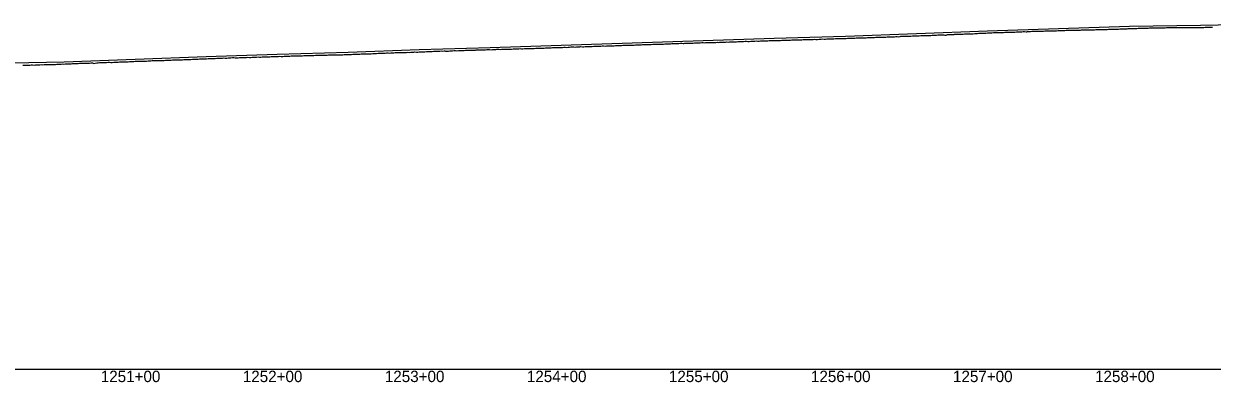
# Model space of a CAD drawing. Extents: x -3793 to 50787, y -1075 to 6138.
# Drawn here: x 12399 to 13236, y 2991 to 3243 of the extents above; entities that cross this region are included whole.
import ezdxf

# ---------------------------------------------------------------- set-up
doc = ezdxf.new("R2010")
doc.units = 0
for name, color, linetype in [('RD_DDB_Profile_EX', 7, 'Continuous'), ('RD_DDB_Profile_PR', 7, 'Continuous'), ('RD_DDB_StaTX', 7, 'Continuous'), ('RD_GPK_Profile_Cell', 7, 'Continuous')]:
    doc.layers.add(name, color=color, linetype=linetype)

msp = doc.modelspace()

# ---------------------------------------------------------------- linework, layer by layer
at = {"layer": 'RD_DDB_Profile_EX'}
for points in [[(13072.306264, 3236.75838), (13073.304099, 3236.70882), (13074.302047, 3236.758805), (13075.292662, 3236.857655), (13075.862268, 3236.857435), (13076.297838, 3236.857915), (13077.295896, 3236.90776), (13078.294157, 3236.956925), (13079.572775, 3236.95617), (13080.577836, 3237.006365), (13081.575804, 3237.15508), (13082.573912, 3237.155535), (13083.179478, 3237.215955), (13083.571855, 3237.254535), (13084.569685, 3237.25478), (13085.574724, 3237.25486), (13086.572591, 3237.354305), (13087.577599, 3237.3546), (13088.568537, 3237.35463), (13089.573545, 3237.404485), (13090.571408, 3237.404325), (13091.569215, 3237.453445), (13092.574194, 3237.453595), (13093.572001, 3237.50288), (13094.576979, 3237.502865), (13095.567796, 3237.403175), (13096.565616, 3237.55208), (13097.813897, 3237.688355), (13098.568459, 3237.8011), (13099.57336, 3237.80105), (13100.571042, 3237.75032), (13101.575949, 3237.800195), (13102.616794, 3237.85), (13103.566623, 3237.84777), (13104.571868, 3237.69821), (13105.131107, 3237.837095), (13105.571994, 3237.945745), (13106.577408, 3237.945795), (13107.577653, 3237.99183), (13108.575683, 3238.08816), (13109.572659, 3238.138465), (13110.572439, 3238.08537), (13111.57772, 3238.13844), (13112.577541, 3238.18377), (13113.875604, 3238.182045), (13114.872886, 3238.18296), (13115.870396, 3238.234645), (13116.867801, 3238.28622), (13117.872954, 3238.335305), (13118.870455, 3238.33979), (13119.867865, 3238.39037), (13120.86535, 3238.43813), (13121.870692, 3238.44062), (13122.868177, 3238.49099), (13123.871794, 3238.49097), (13124.869342, 3238.49199), (13125.874521, 3238.541645), (13127.082736, 3238.551605), (13127.869629, 3238.59012), (13128.867196, 3238.641445), (13129.872629, 3238.689575), (13130.870198, 3238.641615), (13131.867767, 3238.68831), (13132.865404, 3238.786915), (13133.870775, 3238.83896), (13134.399946, 3238.812585), (13134.868387, 3238.78972), (13135.866127, 3238.79165), (13136.863787, 3238.89099), (13137.875257, 3238.987915), (13138.872996, 3238.98792), (13139.870656, 3238.99108), (13140.868395, 3238.94045), (13141.873842, 3238.98604), (13142.871573, 3238.985775), (13143.653405, 3239.039225), (13144.651288, 3239.03983), (13145.649082, 3239.08885), (13146.660711, 3239.089555), (13147.658595, 3239.139395), (13148.656387, 3239.18838), (13149.034366, 3239.207245), (13149.654377, 3239.238075), (13150.652334, 3239.23678), (13151.658457, 3239.23691), (13152.656528, 3239.238625), (13153.660107, 3239.281735), (13154.658059, 3239.33018), (13155.656127, 3239.3276), (13156.654132, 3239.3779), (13157.660383, 3239.42734), (13158.658636, 3239.3716), (13159.656753, 3239.42185), (13160.660469, 3239.381655), (13161.658725, 3239.47849), (13162.664934, 3239.57472), (13163.668785, 3239.622465), (13164.661486, 3239.62139), (13165.659763, 3239.57025), (13166.663611, 3239.61644), (13167.662063, 3239.66361)], [(13167.662063, 3239.66361), (13168.668374, 3239.66355), (13169.666848, 3239.70879), (13170.665122, 3239.76112), (13170.985995, 3239.76072), (13171.663507, 3239.75581), (13172.662174, 3239.80617), (13173.674111, 3239.86908), (13174.692091, 3239.91589), (13175.647174, 3239.914745), (13176.495886, 3239.963505), (13177.499968, 3240.018275), (13178.496861, 3240.01596), (13179.501313, 3240.01219), (13180.498485, 3240.06419), (13181.502407, 3240.11442), (13182.499575, 3240.16466), (13183.504027, 3240.2114), (13184.49436, 3240.26329), (13185.620414, 3240.254215), (13186.495987, 3240.208925), (13187.492701, 3240.31275), (13188.4972, 3240.37356), (13189.494352, 3240.420725), (13190.498629, 3240.370725), (13191.495587, 3240.46975), (13192.500087, 3240.516925), (13192.937624, 3240.53987), (13193.497042, 3240.558655), (13194.495043, 3240.550515), (13195.519098, 3240.578595), (13196.496773, 3240.52966), (13197.493571, 3240.57058), (13198.49812, 3240.620155), (13199.49528, 3240.581695), (13200.492105, 3240.630505), (13201.496706, 3240.62992), (13202.493899, 3240.63098), (13203.498179, 3240.67693), (13204.495376, 3240.728175), (13205.493597, 3240.727905), (13206.490459, 3240.727855), (13207.572044, 3240.7261), (13208.492305, 3240.72811), (13209.496627, 3240.72595), (13210.73181, 3240.779935), (13211.727999, 3240.778465), (13212.716518, 3240.776345), (13213.713849, 3240.727335), (13214.889253, 3240.77705), (13215.715467, 3240.7771), (13216.712546, 3240.82777), (13217.717349, 3240.7788), (13218.714428, 3240.78055), (13219.711508, 3240.83001), (13220.710047, 3240.827075), (13221.707316, 3240.775145), (13222.206463, 3240.79933), (13222.711973, 3240.82241), (13223.709128, 3240.822785), (13224.713803, 3240.878005), (13225.711171, 3240.826885), (13226.708326, 3240.82853), (13227.713176, 3240.871645), (13228.710331, 3240.8248), (13229.715232, 3240.87477), (13230.712467, 3240.920365), (13231.709702, 3240.92041), (13232.714424, 3240.97168), (13233.711902, 3240.97324), (13234.716823, 3241.023375), (13235.714058, 3241.06842)], [(12785.161714, 3227.131865), (12786.1683, 3227.13607), (12787.170487, 3226.94517), (12788.164201, 3227.17857), (12789.166399, 3227.237655), (12790.164483, 3227.243325), (12790.491087, 3227.25927), (12791.166854, 3227.28867), (12792.169305, 3227.240745), (12793.16327, 3227.158285), (12794.169761, 3227.348135), (12795.172211, 3227.393415), (12796.165543, 3227.39367), (12797.172358, 3227.4871), (12798.166415, 3227.48717), (12799.169122, 3227.489035), (12800.171829, 3227.583735), (12801.170409, 3227.58551), (12802.173124, 3227.583785), (12803.167376, 3227.587345), (12804.170109, 3227.72815), (12805.176804, 3227.735715), (12806.171327, 3227.78912), (12807.159993, 3227.77991), (12808.162271, 3227.73218), (12809.161123, 3227.829945), (12810.163394, 3227.92425), (12810.607658, 3227.923805), (12811.607457, 3227.97565), (12812.607261, 3227.977445), (12813.608652, 3227.97141), (12814.608492, 3227.93842), (12815.608331, 3228.035945), (12816.601985, 3228.085405), (12817.609091, 3228.131475), (12818.608943, 3228.179205), (12819.759926, 3228.18809), (12820.603512, 3228.23359), (12821.610676, 3228.28317), (12822.610557, 3228.284335), (12823.604704, 3228.32994), (12824.604578, 3228.28841), (12825.61175, 3228.288015), (12826.605897, 3228.38735), (12827.077136, 3228.387865), (12827.605794, 3228.39193), (12828.60571, 3228.431955), (12829.607192, 3228.47554), (12830.60711, 3228.537525), (12831.607029, 3228.584715), (12832.601218, 3228.630055), (12833.608424, 3228.675595), (12834.608353, 3228.726485), (12835.60259, 3228.68633), (12836.609825, 3228.685405), (12837.609788, 3228.782185), (12838.604033, 3228.834775), (12839.603521, 3228.87755), (12840.610737, 3228.876525), (12841.711556, 3228.926985), (12842.604985, 3228.929475), (12843.60499, 3228.97197), (12844.61223, 3229.07455), (12845.226336, 3229.07937), (12846.226207, 3229.02966), (12847.226078, 3229.083845), (12848.225949, 3229.088), (12849.215929, 3229.138285), (12850.215757, 3229.188545), (12851.2158, 3229.28088), (12852.207881, 3229.340185), (12853.207715, 3229.340435), (12854.207759, 3229.336725), (12855.207594, 3229.38699), (12856.345975, 3229.47974), (12857.207588, 3229.479635), (12858.208176, 3229.48693), (12859.213328, 3229.534995), (12860.212895, 3229.58123), (12861.213473, 3229.67385), (12862.213445, 3229.627475), (12863.213616, 3229.53447), (12863.663185, 3229.601775), (12864.213658, 3229.68067), (12865.206001, 3229.73913), (12866.206303, 3229.688635), (12867.206405, 3229.738375), (12868.207115, 3229.741655), (12869.206804, 3229.748635), (12870.207517, 3229.840955), (12871.207644, 3229.88325), (12872.207448, 3229.913855), (12873.208297, 3229.916815), (12874.213302, 3229.882985), (12875.214143, 3230.021065), (12876.214358, 3230.112885), (12877.214139, 3230.09675), (12878.297605, 3230.050365), (12879.207615, 3230.14303), (12880.208164, 3230.13754), (12881.208501, 3230.144145)], [(12881.208501, 3230.144145), (12882.209495, 3230.19678), (12883.209376, 3230.213315), (12884.209701, 3230.257825), (12885.210705, 3230.306125), (12885.614814, 3230.285125), (12886.191741, 3230.266515), (12887.19141, 3230.351765), (12887.729043, 3230.313365), (12888.726696, 3230.36264), (12889.724042, 3230.404805), (12890.721672, 3230.40474), (12891.718631, 3230.40887), (12892.932024, 3230.54629), (12893.71437, 3230.598165), (12894.720118, 3230.55226), (12895.71792, 3230.64116), (12896.71546, 3230.687855), (12897.713241, 3230.735845), (12898.711008, 3230.73767), (12899.708533, 3230.739745), (12900.249234, 3230.76797), (12900.706376, 3230.785605), (12901.704107, 3230.829055), (12902.702047, 3230.9255), (12903.700245, 3230.930465), (12904.697692, 3230.92748), (12905.704008, 3230.974735), (12906.702179, 3231.034745), (12907.699674, 3231.03691), (12908.698028, 3230.852895), (12909.700544, 3230.812865), (12910.698857, 3231.097195), (12911.696938, 3231.096855), (12912.694659, 3231.10859), (12913.692923, 3231.20443), (12914.883653, 3231.28372), (12915.697633, 3231.24439), (12916.695914, 3231.264015), (12917.694051, 3231.351355), (12918.692318, 3231.39449), (12919.690577, 3231.34633), (12920.691879, 3231.39828), (12921.69001, 3231.453165), (12922.200863, 3231.45416), (12922.688258, 3231.45177), (12923.686632, 3231.500305), (12924.666923, 3231.5006), (12925.665277, 3231.503435), (12926.663623, 3231.5175), (12927.661961, 3231.57122), (12928.660292, 3231.66415), (12929.658654, 3231.66397), (12930.657248, 3231.66474), (12931.664819, 3231.712845), (12932.663417, 3231.77011), (12933.662009, 3231.819475), (12934.660597, 3231.818905), (12935.659179, 3231.825685), (12936.835283, 3231.834085), (12937.656564, 3231.8789), (12938.664463, 3231.932385), (12939.663329, 3231.981305), (12940.662192, 3231.98025), (12941.661054, 3232.031665), (12942.659913, 3232.12943), (12943.658769, 3232.127245), (12944.152492, 3232.12741), (12944.657774, 3232.1309), (12945.656925, 3232.179625), (12946.66517, 3232.183035), (12947.664332, 3232.23035), (12948.663495, 3232.280275), (12949.662658, 3232.235475), (12950.661823, 3232.23542), (12951.661048, 3232.33132), (12952.656175, 3232.37787), (12953.664769, 3232.42916), (12954.664273, 3232.43047), (12955.663782, 3232.47687), (12956.663296, 3232.42988), (12957.662815, 3232.43128), (12958.786912, 3232.493445), (12959.634781, 3232.577135), (12960.304736, 3232.62826), (12961.304005, 3232.676205), (12962.30327, 3232.627555), (12963.30283, 3232.627155), (12964.302092, 3232.72681), (12965.301352, 3232.73009), (12966.306248, 3232.779285), (12967.305477, 3232.82693), (12968.304891, 3232.82636), (12969.304299, 3232.873935), (12970.304026, 3232.923275), (12971.308754, 3232.97429), (12972.308157, 3232.97181), (12973.421331, 3232.978635), (12974.30742, 3233.02422), (12975.298853, 3233.07282), (12976.304059, 3233.075415)], [(12976.304059, 3233.075415), (12976.920737, 3233.125515), (12977.925212, 3233.12439), (12978.921085, 3233.176505), (12979.916619, 3233.228675), (12980.912204, 3233.280805), (12981.917315, 3233.233945), (12982.913143, 3233.2844), (12983.908972, 3233.33513), (12984.904972, 3233.38611), (12985.909911, 3233.387525), (12986.905739, 3233.43946), (12988.055751, 3233.4497), (12988.906876, 3233.49163), (12989.90301, 3233.54237), (12990.899145, 3233.54431), (12991.895323, 3233.596475), (12992.900691, 3233.64672), (12993.892223, 3233.696775), (12994.888364, 3233.698585), (12995.372961, 3233.723795), (12995.885035, 3233.750135), (12996.89062, 3233.750125), (12997.88951, 3233.80095), (12998.887094, 3233.851705), (12999.892778, 3233.901635), (13000.892786, 3233.902485), (13001.889253, 3233.90327), (13002.890367, 3233.904175), (13003.895948, 3234.00375), (13004.89463, 3234.004545), (13005.893358, 3234.055385), (13006.887887, 3234.155645), (13007.897615, 3234.10571), (13008.896349, 3234.156365), (13010.00738, 3234.21272), (13010.888248, 3234.257285), (13011.899128, 3234.307285), (13012.892166, 3234.35753), (13013.890405, 3234.35833), (13014.8989, 3234.308925), (13015.897318, 3234.50828), (13016.410199, 3234.557595), (13017.408796, 3234.558375), (13018.407311, 3234.608745), (13019.405826, 3234.609465), (13020.411638, 3234.610705), (13021.410153, 3234.710675), (13022.408668, 3234.71062), (13023.39842, 3234.76053), (13024.6418, 3234.811125), (13025.411096, 3234.811755), (13026.416756, 3234.81191), (13027.415183, 3234.911665), (13028.413609, 3234.912885), (13029.41211, 3234.96314), (13030.410538, 3235.06236), (13031.408966, 3235.11259), (13031.959009, 3235.08517), (13032.407355, 3235.06383), (13033.412913, 3235.114775), (13034.411336, 3235.115485), (13035.416482, 3235.21375), (13036.414822, 3235.16554), (13037.413161, 3235.16568), (13038.411584, 3235.26526), (13039.409912, 3235.314235), (13040.415378, 3235.41563), (13041.413632, 3235.465035), (13042.411886, 3235.51444), (13043.410227, 3235.563855), (13044.408481, 3235.565065), (13045.413536, 3235.564935), (13046.593429, 3235.578385), (13047.417181, 3235.41808), (13048.415438, 3235.41796), (13049.296724, 3235.813255), (13050.29497, 3235.814355), (13051.293217, 3235.86425), (13052.303315, 3235.86592), (13053.301474, 3235.915215), (13053.910639, 3235.94594), (13054.294686, 3235.965265), (13055.300329, 3235.96489), (13056.298574, 3236.014095), (13057.307584, 3236.06388), (13058.305655, 3236.113655), (13059.303805, 3236.112365), (13060.309141, 3236.115115), (13061.307286, 3236.21322), (13062.305192, 3236.2129), (13063.30325, 3236.263105), (13064.291037, 3236.312255), (13065.299281, 3236.41193), (13066.294256, 3236.41236), (13067.309219, 3236.41182), (13068.545058, 3236.473775), (13069.305182, 3236.51061), (13070.303137, 3236.609755), (13071.30831, 3236.70962), (13072.306264, 3236.75838)], [(12595.18229, 3220.917655), (12596.179708, 3220.93725), (12597.183113, 3220.978635), (12598.180536, 3220.98066), (12599.183936, 3221.051895), (12600.243634, 3221.062645), (12601.184864, 3221.115985), (12602.182411, 3221.15857), (12603.178695, 3221.15884), (12604.182196, 3221.200265), (12605.260439, 3221.213145), (12606.264547, 3221.21172), (12607.560844, 3221.29361), (12608.534436, 3221.33665), (12609.532153, 3221.269425), (12610.532749, 3221.308945), (12611.53669, 3221.37191), (12612.53861, 3221.373765), (12613.53501, 3221.41641), (12614.536917, 3221.511955), (12614.878053, 3221.49483), (12615.533435, 3221.432655), (12616.535513, 3221.43412), (12617.532093, 3221.46931), (12618.532893, 3221.442675), (12619.530743, 3221.57771), (12620.531541, 3221.586655), (12621.529385, 3221.571665), (12622.530244, 3221.572965), (12623.528267, 3221.607995), (12624.529246, 3221.69517), (12625.526012, 3221.744495), (12626.535868, 3221.80815), (12627.532631, 3221.85754), (12628.530665, 3221.856675), (12629.531642, 3221.81503), (12630.530563, 3221.942775), (12631.531715, 3221.929625), (12632.528673, 3221.97138), (12633.531093, 3222.04359), (12634.528055, 3222.042575), (12635.530473, 3222.078955), (12636.527439, 3222.12817), (12636.829683, 3222.128495), (12637.52999, 3222.12859), (12638.527152, 3222.12754), (12639.528483, 3222.220925), (12640.526929, 3222.29784), (12641.535868, 3222.24693), (12642.584716, 3222.260745), (12643.586412, 3222.31895), (12644.583336, 3222.36824), (12645.585336, 3222.368835), (12646.436473, 3222.495595), (12647.353757, 3222.53258), (12648.34842, 3222.60685), (12649.351012, 3222.628885), (12650.346788, 3222.67372), (12651.464102, 3222.666705), (12652.344042, 3222.69877), (12653.351913, 3222.771535), (12654.353461, 3222.81537), (12655.349212, 3222.817265), (12656.351829, 3222.73086), (12657.346512, 3222.826265), (12658.349128, 3222.863615), (12658.781312, 3222.86459), (12659.344062, 3222.85229), (12660.345687, 3223.07057), (12661.34833, 3223.12188), (12662.344052, 3223.11716), (12663.345693, 3223.161135), (12664.346741, 3223.158905), (12665.349383, 3223.165095), (12666.352033, 3223.239595), (12667.346775, 3223.178855), (12668.349443, 3223.278595), (12669.345137, 3223.297925), (12670.346854, 3223.24788), (12671.342538, 3223.34306), (12672.345208, 3223.35473), (12673.415731, 3223.37456), (12674.342636, 3223.520085), (12675.350711, 3223.48328), (12676.345477, 3223.50761), (12677.348174, 3223.62813), (12678.343853, 3223.60221), (12679.345637, 3223.690355), (12680.348334, 3223.68401), (12680.732941, 3223.684485), (12681.344031, 3223.68484), (12682.345844, 3223.78416), (12683.404348, 3223.78509), (12684.406534, 3223.83441), (12685.410311, 3223.939595), (12686.409477, 3223.96429), (12687.411675, 3224.007785), (12688.406596, 3223.99855), (12689.408993, 3224.047665), (12689.868477, 3224.09275), (12690.864861, 3224.093365)], [(12690.864861, 3224.093365), (12691.866756, 3224.16412), (12692.867594, 3224.223), (12693.863062, 3224.20753), (12694.864976, 3224.23389), (12695.367361, 3224.23536), (12695.865839, 3224.220465), (12696.868669, 3224.157735), (12697.864174, 3224.15199), (12698.865042, 3224.42761), (12699.867019, 3224.420735), (12700.862515, 3224.371365), (12701.863594, 3224.473825), (12702.866231, 3224.477795), (12703.861119, 3224.45435), (12704.869179, 3224.47844), (12705.864705, 3224.51287), (12706.859594, 3224.46813), (12707.868499, 3224.584375), (12708.863388, 3224.68962), (12710.00178, 3224.7055), (12710.867014, 3224.69833), (12711.861945, 3224.74788), (12712.870894, 3224.8242), (12713.865824, 3224.873825), (12714.86139, 3224.755295), (12715.868864, 3224.73955), (12716.864429, 3224.918405), (12717.31899, 3224.96256), (12717.867154, 3225.026845), (12718.868374, 3225.06753), (12719.863989, 3225.022375), (12720.866088, 3225.04147), (12721.867104, 3225.03765), (12722.862724, 3225.03188), (12723.865686, 3225.073805), (12724.866703, 3225.186305), (12725.894757, 3225.1893), (12726.890599, 3225.210795), (12727.891368, 3225.117825), (12728.894669, 3225.27641), (12729.890522, 3225.27569), (12730.261901, 3225.27701), (12731.364928, 3225.34085), (12731.953409, 3225.40041), (12732.365101, 3225.425735), (12733.365446, 3225.421435), (12734.259436, 3225.33305), (12735.357693, 3225.475515), (12736.25508, 3225.52136), (12737.361785, 3225.41973), (12738.262719, 3225.510875), (12739.353989, 3225.54352), (12740.354619, 3225.544205), (12741.355249, 3225.56623), (12742.260835, 3225.612275), (12743.347549, 3225.683875), (12744.348175, 3225.680045), (12745.257042, 3225.680785), (12746.264132, 3225.684135), (12746.587829, 3225.71773), (12747.345551, 3225.782475), (12748.346474, 3225.87858), (12749.347028, 3225.85043), (12750.261589, 3225.850775), (12751.340221, 3225.890415), (12752.341142, 3225.94504), (12753.342063, 3226.024545), (12753.905039, 3226.02482), (12754.259571, 3226.024835), (12755.338437, 3225.95421), (12756.339661, 3225.99626), (12757.340885, 3226.042305), (12758.342109, 3226.070255), (12759.334614, 3226.214125), (12760.335506, 3226.260055), (12761.258446, 3226.21398), (12762.329549, 3226.26164), (12763.253864, 3226.307485), (12764.336523, 3226.328375), (12765.262283, 3226.32813), (12766.33049, 3226.418115), (12767.33202, 3226.414065), (12768.539458, 3226.460045), (12769.175199, 3226.45608), (12770.168504, 3226.507445), (12771.17459, 3226.57013), (12772.167529, 3226.624755), (12773.168578, 3226.64181), (12774.170276, 3226.662735), (12775.167957, 3226.713035), (12776.169731, 3226.71568), (12777.163226, 3226.68401), (12778.165172, 3226.76907), (12779.17151, 3226.91346), (12780.164991, 3226.91447), (12781.166942, 3226.723725), (12782.173279, 3226.842035), (12783.173878, 3227.032835), (12784.167997, 3227.081365), (12785.161714, 3227.131865)], [(12398.152446, 3214.175745), (12399.160078, 3214.27357), (12400.153836, 3214.269405), (12401.154084, 3214.221535), (12402.154332, 3214.22369), (12402.67897, 3214.27507), (12403.155446, 3214.32161)], [(12403.155446, 3214.32161), (12404.155624, 3214.37354), (12405.155593, 3214.378645), (12406.14949, 3214.327475), (12407.157063, 3214.42356), (12408.150754, 3214.51931), (12409.150929, 3214.474285), (12410.158497, 3214.575015), (12411.152122, 3214.62359), (12412.152229, 3214.47825), (12413.152336, 3214.623885), (12414.153373, 3214.66987), (12415.153479, 3214.674395), (12416.147288, 3214.721535), (12417.31339, 3214.770155), (12418.149762, 3214.77205), (12419.143576, 3214.770485), (12420.143581, 3214.769125), (12421.151098, 3214.770695), (12422.144906, 3214.867765), (12423.144911, 3214.963795), (12424.138711, 3214.963615), (12424.6306, 3215.01186), (12425.146214, 3215.062375), (12426.146169, 3215.11345), (12427.139913, 3214.964155), (12428.139867, 3215.1078), (12429.147356, 3215.2041), (12430.238755, 3215.255995), (12431.238718, 3215.20813), (12432.238669, 3215.259025), (12433.238591, 3215.3563), (12434.232174, 3215.35327), (12435.239699, 3215.304965), (12436.239623, 3215.40347), (12437.239547, 3215.404115), (12438.233299, 3215.55106), (12439.265019, 3215.554825), (12440.233108, 3215.648015), (12441.232992, 3215.647405), (12442.240499, 3215.6947), (12443.2342, 3215.74443), (12444.234197, 3215.743835), (12445.23408, 3215.74321), (12446.233963, 3215.840845), (12446.582229, 3215.840105), (12447.227618, 3215.84027), (12448.235104, 3215.4945), (12449.23495, 3215.541995), (12450.234796, 3215.885825), (12451.234642, 3215.935735), (12452.228267, 3216.034015), (12453.22811, 3216.03382), (12453.899439, 3216.099035), (12454.23561, 3216.12916), (12455.23542, 3216.128745), (12456.23523, 3216.12829), (12457.2288, 3216.225145), (12458.230101, 3216.273635), (12459.229844, 3216.27262), (12460.237269, 3216.220475), (12461.230597, 3216.21758), (12462.230338, 3216.416035), (12463.392934, 3216.415375), (12464.392755, 3216.464185), (12465.3848, 3216.464125), (12466.384575, 3216.51236), (12467.384383, 3216.511475), (12468.533858, 3216.56784), (12469.383891, 3216.60896), (12470.38988, 3216.65864), (12471.389649, 3216.65767), (12472.389387, 3216.70616), (12473.381381, 3216.7559), (12474.381134, 3216.75476), (12475.380858, 3216.85328), (12475.851068, 3216.87669), (12476.386886, 3216.903185), (12477.386587, 3216.951605), (12478.44822, 3216.953095), (12479.387634, 3216.997585), (12480.389075, 3216.993955), (12481.381579, 3216.99333), (12482.387694, 3217.04466), (12483.389107, 3217.1432), (12484.390722, 3217.14151), (12485.388279, 3217.140175), (12486.389076, 3217.185465), (12487.389808, 3217.18416), (12488.395988, 3217.3305), (12489.388433, 3217.429535), (12490.485487, 3217.429245), (12491.390193, 3217.42688), (12492.390828, 3217.42425), (12493.391898, 3217.466335), (12494.39787, 3217.556505), (12495.398618, 3217.598785), (12496.399708, 3217.51805), (12497.392121, 3217.51257), (12497.802697, 3217.59346), (12498.610126, 3217.743655)], [(12498.610126, 3217.743655), (12499.610562, 3217.794505), (12500.610605, 3217.83271), (12501.603491, 3217.880565), (12502.60881, 3217.879035), (12503.608834, 3217.927865), (12504.609354, 3217.98646), (12505.119907, 3217.98586), (12505.614945, 3217.985235), (12506.608, 3217.986555), (12507.607639, 3218.075925), (12508.607661, 3218.033295), (12509.613778, 3217.974385), (12510.613781, 3218.058975), (12511.60704, 3218.22697), (12512.612023, 3218.129675), (12513.612024, 3218.191815), (12514.612737, 3218.23688), (12515.605441, 3218.171275), (12516.610835, 3218.265175), (12517.611024, 3218.40162), (12518.611, 3218.4326), (12519.754326, 3218.513135), (12520.60993, 3218.559705), (12521.609927, 3218.550825), (12522.610147, 3218.5854), (12523.615375, 3218.639335), (12524.643776, 3218.6475), (12525.637873, 3218.65189), (12526.642429, 3218.73815), (12527.071536, 3218.757905), (12527.64398, 3218.784805), (12528.645591, 3218.82479), (12529.639177, 3218.91564), (12530.644359, 3218.957265), (12531.645214, 3218.90305), (12532.756403, 3218.999685), (12533.760336, 3219.015525), (12534.758563, 3219.05773), (12535.75647, 3219.11451), (12536.75965, 3219.165445), (12537.758722, 3219.20777), (12538.7578, 3219.25004), (12539.759811, 3219.3084), (12540.758881, 3219.26492), (12541.757141, 3219.271205), (12542.761192, 3219.314985), (12543.760325, 3219.36414), (12544.757462, 3219.463235), (12545.761516, 3219.59987), (12546.759825, 3219.591405), (12547.758968, 3219.512195), (12549.023166, 3219.519765), (12549.760182, 3219.50475), (12550.759386, 3219.588935), (12551.762656, 3219.646635), (12552.761864, 3219.65277), (12553.759016, 3219.61638), (12554.763129, 3219.70221), (12555.762344, 3219.73615), (12556.760735, 3219.776855), (12557.764902, 3219.734795), (12558.762081, 3219.72105), (12559.761373, 3219.804505), (12560.765541, 3219.87014), (12561.76396, 3219.887725), (12562.761998, 3219.970915), (12563.854831, 3220.036745), (12564.853753, 3219.93521), (12565.854111, 3219.975475), (12566.856845, 3220.09168), (12567.696497, 3220.17396), (12568.191237, 3220.125315), (12569.186966, 3220.092935), (12570.189849, 3220.101105), (12571.18693, 3220.144685), (12572.189935, 3220.221435), (12573.18709, 3220.272805), (12574.182927, 3220.297365), (12575.187249, 3220.297145), (12576.183086, 3220.341025), (12577.187409, 3220.37563), (12578.292005, 3220.44229), (12579.18639, 3220.464635), (12580.183614, 3220.457975), (12581.186775, 3220.457725), (12582.183993, 3220.501145), (12583.187161, 3220.593425), (12584.184373, 3220.644375), (12585.18032, 3220.680885), (12585.609214, 3220.680635), (12586.183565, 3220.68776), (12587.180875, 3220.73844), (12588.184168, 3220.737825), (12589.181477, 3220.788505), (12590.184771, 3220.83052), (12591.18208, 3220.803245), (12592.185374, 3220.802685), (12593.182711, 3220.84589), (12594.178881, 3220.87456), (12595.18229, 3220.917655)]]:
    msp.add_lwpolyline(points, dxfattribs=at)
at = {"layer": 'RD_DDB_Profile_PR'}
for points in [[(12877.33, 3231.692), (12927.33, 3233.1535), (12977.33, 3234.725), (13027.33, 3236.503), (13077.33, 3238.5095), (13127.33, 3240.1635), (13177.33, 3241.609), (13227.33, 3242.455), (13277.33, 3243.4115)], [(12377.33, 3215.5805), (12427.33, 3216.5915), (12477.33, 3218.549), (12527.33, 3220.37), (12577.33, 3221.984), (12627.33, 3223.4475), (12677.33, 3225.226), (12727.33, 3226.77), (12777.33, 3228.298), (12827.33, 3229.99), (12877.33, 3231.692)]]:
    msp.add_lwpolyline(points, dxfattribs=at)
at = {"layer": 'RD_GPK_Profile_Cell'}
msp.add_line((1000, 3000), (46549.603806, 3000), dxfattribs=at)

# ---------------------------------------------------------------- texts
at = {"layer": 'RD_DDB_StaTX'}
for s, p in [('1251+00', (12453.125471, 2991)), ('1251+00', (12453.125471, 2991)), ('1252+00', (12553.125471, 2991)), ('1252+00', (12553.125471, 2991)), ('1253+00', (12653.125471, 2991)), ('1253+00', (12653.125471, 2991)), ('1254+00', (12753.125471, 2991)), ('1254+00', (12753.125471, 2991)), ('1255+00', (12853.125471, 2991)), ('1255+00', (12853.125471, 2991)), ('1256+00', (12953.125471, 2991)), ('1256+00', (12953.125471, 2991)), ('1257+00', (13053.125471, 2991)), ('1257+00', (13053.125471, 2991)), ('1258+00', (13153.125471, 2991)), ('1258+00', (13153.125471, 2991))]:
    msp.add_text(s, height=8, dxfattribs=at).set_placement(p)

doc.saveas('drawing.dxf')
